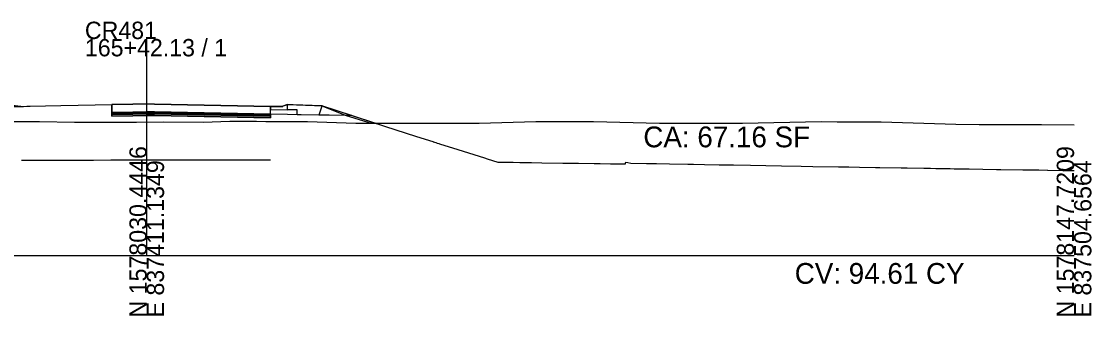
# Model space of a CAD drawing. Extents: x -26 to 303, y -16 to 6048.
# Drawn here: x 129.7 to 302.8, y 4490.3 to 4537.8 of the extents above; entities that cross this region are included whole.
import ezdxf

# ---------------------------------------------------------------- set-up
doc = ezdxf.new("R2010")
doc.units = 0
for name, color, linetype in [('ASPHALT_19MM1', 7, 'Continuous'), ('ASPHALT_9_5MM1', 7, 'Continuous'), ('CONST_DCH', 7, 'Continuous'), ('CONST_LV3', 7, 'Continuous'), ('Default', 7, 'Continuous'), ('DTM_P_FINISHED_GRADE', 7, 'Continuous'), ('DTM_P_FINISHED_GRADE2', 7, 'Continuous'), ('DTM_TEMP_DROP', 7, 'Continuous'), ('DTM_X_FLOW_ARROWS', 7, 'Continuous'), ('DTM_X_GROUND', 7, 'Continuous'), ('TRANS_PAVED_SHOULDERS', 7, 'Continuous'), ('X_PROFILES_1', 7, 'Continuous'), ('XS_CELL', 7, 'Continuous'), ('XS_M_SHAPES_EARTHWORK', 7, 'Continuous'), ('XS_P_ASPHALT', 7, 'Continuous'), ('XS_P_CONCRETE', 7, 'Continuous'), ('XS_P_GROUND', 7, 'Continuous'), ('XS_P_SHOULDER', 7, 'Continuous'), ('XS_P_SUBGRADE_GRANULAR', 7, 'Continuous'), ('XS_P_SUBGRADE_GRANULAR_B', 7, 'Continuous'), ('XS_SHEET_EW_TX_AREA', 7, 'Continuous'), ('XS_SHEET_EW_TX_VOLUME', 7, 'Continuous')]:
    doc.layers.add(name, color=color, linetype=linetype)

msp = doc.modelspace()

# ---------------------------------------------------------------- linework, layer by layer
at = {"layer": 'ASPHALT_19MM1'}
msp.add_lwpolyline([(147.77, 4522.87), (144.36, 4522.8), (144.36, 4522.53), (147.77, 4522.6), (150, 4522.64), (151.27, 4522.62), (170.01, 4522.24), (170.01, 4522.51), (151.27, 4522.89), (150, 4522.91), (147.77, 4522.87)], dxfattribs=at)
at = {"layer": 'ASPHALT_9_5MM1'}
msp.add_lwpolyline([(147.77, 4523.2), (144.36, 4523.13), (144.36, 4523.01), (147.77, 4523.08), (150, 4523.12), (151.27, 4523.1), (170.01, 4522.72), (170.01, 4522.85), (151.27, 4523.22), (150, 4523.25), (147.77, 4523.2)], dxfattribs=at)
at = {"layer": 'CONST_LV3'}
for points in [[(147.77, 4524.47), (144.36, 4524.4), (144.36, 4523.13), (147.77, 4523.2), (150, 4523.25), (151.27, 4523.22), (170.01, 4522.85), (170.01, 4524.12), (151.27, 4524.49), (150, 4524.52), (147.77, 4524.47)], [(170, 4524.12), (170, 4523.62), (172.78, 4523.57), (172.78, 4524.4), (172.02, 4524.17), (172.02, 4524.08), (170, 4524.12)], [(178.32, 4524.2), (173.68, 4524.37), (172.78, 4524.4)], [(206.86, 4515.06), (205.12, 4515.59), (204.71, 4515.72), (200.36, 4517.08), (197.42, 4518.02), (197.33, 4518.04), (197.25, 4518.07), (197.02, 4518.14), (196.8, 4518.21), (196.61, 4518.27), (196.42, 4518.34), (196.38, 4518.35), (196.35, 4518.36), (193.68, 4519.21), (188.54, 4520.87), (186.18, 4521.63), (178.32, 4524.2), (173.68, 4524.37), (172.78, 4524.4)], [(186.89, 4521.42), (183.3, 4522.58), (178.34, 4524.2), (173.65, 4524.37), (172.79, 4524.4)], [(174.31, 4522.77), (174.31, 4523.54), (172.79, 4523.57)]]:
    msp.add_lwpolyline(points, dxfattribs=at)
at = {"layer": 'Default'}
msp.add_lwpolyline([(170, 4524.12), (170, 4524.12), (170, 4524.12)], dxfattribs=at)
at = {"layer": 'DTM_P_FINISHED_GRADE'}
msp.add_lwpolyline([(144.36, 4524.4), (147.77, 4524.47), (150, 4524.52), (151.27, 4524.49), (170.01, 4524.12)], dxfattribs=at)
at = {"layer": 'DTM_P_FINISHED_GRADE2'}
msp.add_lwpolyline([(128.49, 4524.09), (130.08, 4524.12), (130.62, 4524.13), (131.14, 4524.14), (136.08, 4524.24), (150, 4524.52), (163.99, 4524.24), (168.69, 4524.15), (170.01, 4524.12), (171.83, 4524.09), (172.03, 4524.08), (172.03, 4524.09), (172.03, 4524.17), (172.11, 4524.19), (172.79, 4524.4), (177.15, 4524.24), (178.34, 4524.2), (182.27, 4522.65), (186.31, 4521.42), (186.89, 4521.42)], dxfattribs=at)
at = {"layer": 'DTM_X_GROUND'}
for points in [[(127.82, 4524.35), (130.08, 4524.12), (130.62, 4524.13), (131.14, 4524.14), (136.08, 4524.24), (150, 4524.52), (163.99, 4524.24), (168.69, 4524.15), (170.01, 4524.12), (171.83, 4524.16), (172.03, 4524.17), (172.11, 4524.19), (172.79, 4524.4), (177.15, 4524.24), (178.34, 4524.2), (182.27, 4522.65), (186.31, 4521.42), (186.56, 4521.42), (186.89, 4521.42), (187.03, 4521.42), (187.19, 4521.42), (188.69, 4521.42), (191.34, 4521.41), (193.08, 4521.41), (193.77, 4521.41), (194.36, 4521.41), (197.02, 4521.42), (197.07, 4521.42), (203.7, 4521.41), (203.75, 4521.4), (212.95, 4521.67), (216.18, 4521.67), (219.21, 4521.67), (222.26, 4521.66), (232.97, 4521.4), (236.39, 4521.41), (242.97, 4521.38), (246.38, 4521.39), (259.08, 4521.65), (261.71, 4521.64), (264.29, 4521.63), (266.26, 4521.63), (268.8, 4521.62), (280.88, 4521.24), (284.65, 4521.21), (290.79, 4521.19), (294.72, 4521.16), (300, 4521.14)], [(126.79, 4521.67), (132.67, 4521.67), (138.32, 4521.58), (145.22, 4521.57), (148.33, 4521.57), (152.67, 4521.59), (159.12, 4521.58), (163.42, 4521.72), (167.78, 4521.71), (169.26, 4521.68), (172.1, 4521.68), (176.01, 4521.68), (183.8, 4521.41), (187.03, 4521.42), (193.77, 4521.41), (197.07, 4521.42), (203.75, 4521.41), (212.95, 4521.67), (216.18, 4521.67), (219.21, 4521.67), (222.26, 4521.66), (232.97, 4521.4), (236.39, 4521.41), (242.97, 4521.38), (246.38, 4521.39), (259.08, 4521.65), (261.71, 4521.64), (264.29, 4521.63), (266.26, 4521.63), (268.8, 4521.62), (280.88, 4521.24), (284.65, 4521.21), (290.79, 4521.19), (294.72, 4521.16), (300, 4521.14)]]:
    msp.add_lwpolyline(points, dxfattribs=at)
at = {"layer": 'TRANS_PAVED_SHOULDERS'}
msp.add_lwpolyline([(147.77, 4523.08), (144.36, 4523.01), (144.36, 4522.8), (147.77, 4522.87), (150, 4522.91), (151.27, 4522.89), (170.01, 4522.51), (170.01, 4522.72), (151.27, 4523.1), (150, 4523.12), (147.77, 4523.08)], dxfattribs=at)
at = {"layer": 'XS_CELL'}
for p, q in [((150, 4500), (150, 4535)), ((0, 4500), (150, 4500)), ((150, 4500), (300, 4500))]:
    msp.add_line(p, q, dxfattribs=at)
at = {"layer": 'XS_M_SHAPES_EARTHWORK'}
for points in [[(144.36, 4524.4), (150, 4524.52), (163.99, 4524.24), (168.69, 4524.15), (170.01, 4524.12), (171.83, 4524.16), (172.03, 4524.17), (172.11, 4524.19), (172.79, 4524.4), (177.15, 4524.24), (178.34, 4524.2), (182.27, 4522.65), (179.53, 4522.69), (177.84, 4522.72), (174.96, 4522.76), (174.31, 4522.77), (172.79, 4522.8), (170.01, 4522.85), (170.01, 4522.72), (170.01, 4522.51), (170.01, 4522.24), (151.27, 4522.62), (150, 4522.64), (147.77, 4522.6), (144.36, 4522.53), (144.36, 4522.8), (144.36, 4523.01), (144.36, 4523.13)], [(182.27, 4522.65), (182.27, 4522.65), (186.31, 4521.42), (186.56, 4521.42), (186.89, 4521.42), (183.3, 4522.58), (183.14, 4522.63)]]:
    msp.add_lwpolyline(points, close=True, dxfattribs=at)
at = {"layer": 'XS_P_ASPHALT'}
msp.add_lwpolyline([(170.01, 4524.12), (151.27, 4524.49), (150, 4524.52), (147.77, 4524.47), (144.36, 4524.4)], dxfattribs=at)
at = {"layer": 'XS_P_CONCRETE'}
msp.add_lwpolyline([(170.01, 4524.12), (170.01, 4523.62), (172.79, 4523.57), (172.79, 4524.4), (172.03, 4524.17), (172.03, 4524.08), (170.01, 4524.12)], dxfattribs=at)
at = {"layer": 'XS_P_GROUND'}
for points in [[(206.86, 4515.06), (205.12, 4515.59), (204.71, 4515.72), (200.36, 4517.08), (197.42, 4518.02), (197.33, 4518.04), (197.25, 4518.07), (197.02, 4518.14), (196.8, 4518.21), (196.61, 4518.27), (196.42, 4518.34), (196.38, 4518.35), (196.35, 4518.36), (193.68, 4519.21), (188.54, 4520.87), (186.18, 4521.63), (178.32, 4524.2)], [(186.89, 4521.42), (183.3, 4522.58), (178.34, 4524.2)], [(170, 4515.42), (170, 4515.42), (170, 4515.42), (170, 4515.42), (169.9, 4515.42), (169.9, 4515.42), (167.09, 4515.42), (166.71, 4515.42), (162.98, 4515.41), (161.65, 4515.41), (158.71, 4515.41), (157.08, 4515.41), (156.77, 4515.41), (156.59, 4515.41), (153.76, 4515.41), (151.53, 4515.41), (149.01, 4515.4), (146.47, 4515.4), (144.19, 4515.4), (141.41, 4515.39), (139.33, 4515.39), (136.35, 4515.39), (134.53, 4515.39), (131.54, 4515.38), (131.44, 4515.38), (131.29, 4515.38), (130.8, 4515.38), (129.73, 4515.38)], [(300, 4513.69), (298.52, 4513.71), (298.21, 4513.71), (295.76, 4513.75), (295.71, 4513.75), (294.33, 4513.78), (293.16, 4513.79), (293.12, 4513.79), (291.9, 4513.81), (291.69, 4513.82), (288.15, 4513.87), (288.14, 4513.87), (288.1, 4513.87), (287.45, 4513.88), (283.04, 4513.95), (282.53, 4513.96), (280.59, 4513.99), (279.95, 4514), (277.99, 4514.03), (277.65, 4514.04), (276.8, 4514.05), (275.68, 4514.07), (273.03, 4514.11), (272.99, 4514.11), (272.93, 4514.11), (272.63, 4514.12), (272.05, 4514.13), (268.59, 4514.19), (267.87, 4514.2), (265.27, 4514.24), (263.57, 4514.27), (263.46, 4514.28), (262.82, 4514.29), (261.9, 4514.3), (257.76, 4514.37), (255.88, 4514.41), (252.7, 4514.46), (250.13, 4514.5), (247.65, 4514.55), (244.92, 4514.59), (242.59, 4514.63), (240.25, 4514.67), (238.46, 4514.7), (237.92, 4514.71), (237.53, 4514.72), (234.54, 4514.77), (232.47, 4514.81), (230.83, 4514.83), (228.32, 4514.88), (227.82, 4514.98), (227.42, 4515.07), (227.4, 4514.93), (227.38, 4514.75), (227.37, 4514.75), (226.67, 4514.76), (226.44, 4514.76), (225.03, 4514.78), (223.35, 4514.81), (222.94, 4514.82), (222.9, 4514.82), (222.52, 4514.82), (222.36, 4514.82), (219.83, 4514.86), (217.3, 4514.9), (213.91, 4514.95), (212.24, 4514.98), (210.73, 4515), (210.33, 4515), (209.28, 4515.02), (209.24, 4515.02), (209.02, 4515.02), (208.81, 4515.03), (208.28, 4515.04), (208.18, 4515.04), (208.05, 4515.04), (207.92, 4515.04), (207.81, 4515.04), (207.44, 4515.05), (207.36, 4515.05), (207.18, 4515.05), (207.09, 4515.05), (207.07, 4515.05), (207.04, 4515.05), (207.03, 4515.05), (206.86, 4515.06)], [(298.36, 4513.71), (298.71, 4513.89), (300, 4514.53)]]:
    msp.add_lwpolyline(points, dxfattribs=at)
at = {"layer": 'XS_P_SHOULDER'}
msp.add_lwpolyline([(178.34, 4524.2), (173.65, 4524.37), (172.79, 4524.4)], dxfattribs=at)
at = {"layer": 'XS_P_SUBGRADE_GRANULAR'}
for points in [[(170.01, 4522.85), (151.27, 4523.22), (150, 4523.25), (147.77, 4523.2), (144.36, 4523.13)], [(172.79, 4522.8), (170.01, 4522.85)], [(174.31, 4522.77), (172.79, 4522.8)]]:
    msp.add_lwpolyline(points, dxfattribs=at)
at = {"layer": 'XS_P_SUBGRADE_GRANULAR_B'}
for points in [[(178.34, 4524.2), (178.21, 4523.82), (177.84, 4522.72)], [(177.84, 4522.72), (174.96, 4522.76), (174.31, 4522.77)], [(183.16, 4522.63), (179.53, 4522.69), (177.84, 4522.72)]]:
    msp.add_lwpolyline(points, dxfattribs=at)

# ---------------------------------------------------------------- texts
at = {"layer": 'CONST_DCH'}
msp.add_text('X', height=0.24, dxfattribs=at).set_placement((206.78, 4514.94))
at = {"layer": 'DTM_TEMP_DROP'}
for p in [(186.82, 4521.3), (206.78, 4514.94)]:
    msp.add_text('X', height=0.24, dxfattribs=at).set_placement(p)
at = {"layer": 'DTM_X_FLOW_ARROWS'}
msp.add_text('X', height=0.24, dxfattribs=at).set_placement((298.28, 4513.59))
at = {"layer": 'X_PROFILES_1'}
msp.add_text('X', height=0.24, dxfattribs=at).set_placement((178.24, 4524.08))
at = {"layer": 'XS_CELL'}
for s, p in [('CR481', (140, 4535)), ('165+42.13 / 1', (140, 4532.2))]:
    msp.add_text(s, height=2.8, dxfattribs=at).set_placement(p)
for s, p in [('N 1578030.4446', (150, 4490)), ('N 1578147.7209', (300, 4490)), ('E 837411.1349', (152.8, 4490)), ('E 837504.6564', (302.8, 4490))]:
    msp.add_text(s, height=2.8, rotation=90, dxfattribs=at).set_placement(p)
at = {"layer": 'XS_P_GROUND'}
for p in [(172.72, 4524.28), (178.27, 4524.08)]:
    msp.add_text('X', height=0.24, dxfattribs=at).set_placement(p)
at = {"layer": 'XS_P_SUBGRADE_GRANULAR'}
msp.add_text('X', height=0.24, dxfattribs=at).set_placement((186.82, 4521.3))
at = {"layer": 'XS_SHEET_EW_TX_AREA'}
msp.add_text('CA: 67.16 SF', height=3.36, dxfattribs=at).set_placement((230.33, 4517.5))
at = {"layer": 'XS_SHEET_EW_TX_VOLUME'}
msp.add_text('CV: 94.61 CY', height=3.36, dxfattribs=at).set_placement((254.82, 4495.44))

doc.saveas('drawing.dxf')
